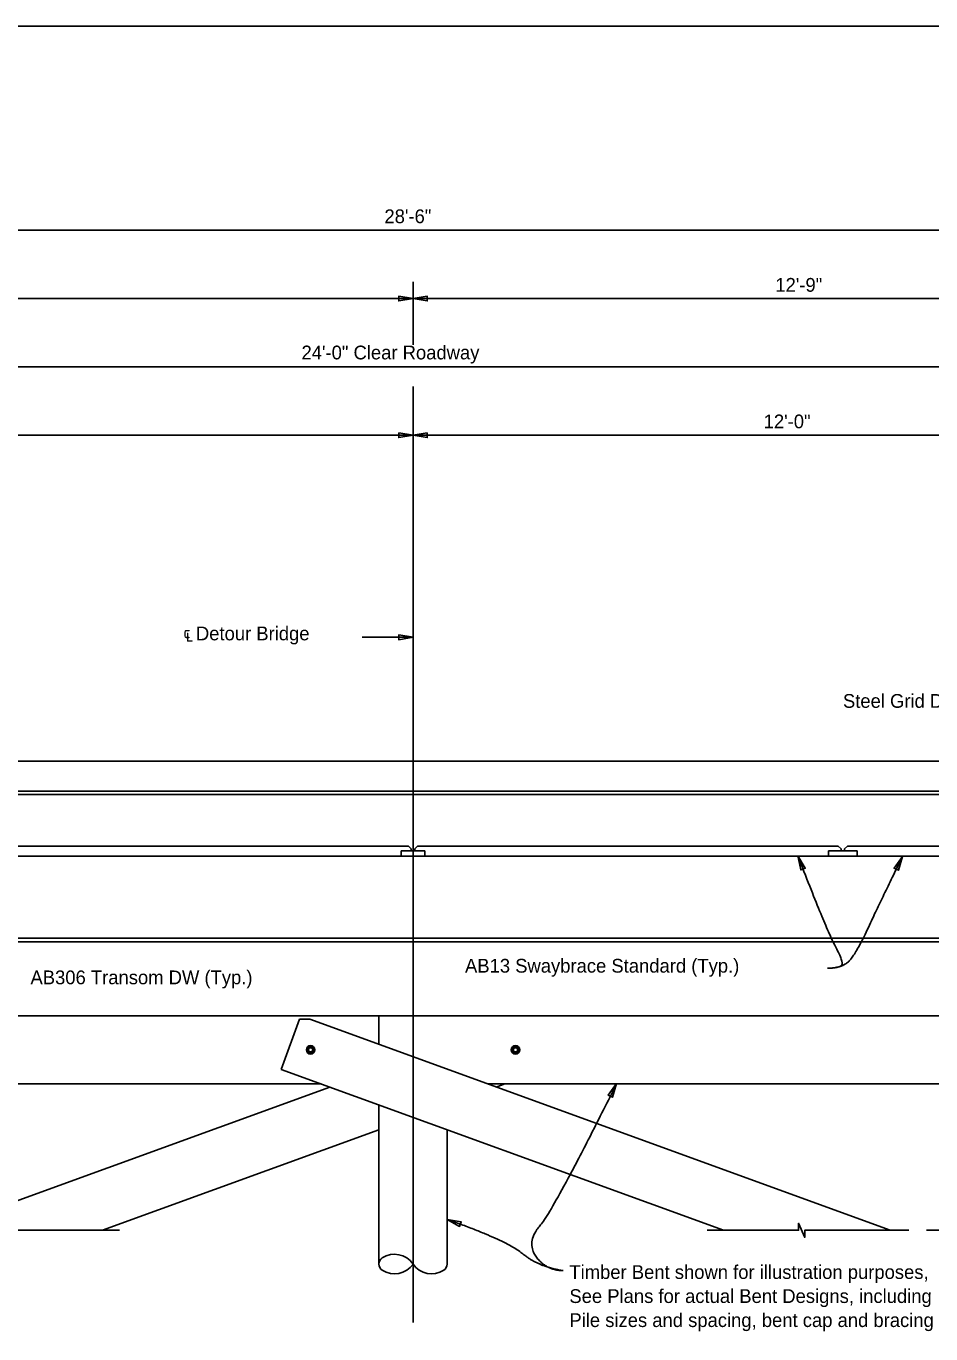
# Model space of a CAD drawing. Extents: x 11137.4 to 11208.2, y 76297.7 to 76332.4.
# Drawn here: x 11151.28 to 11164.53, y 76313.02 to 76332.16 of the extents above; entities that cross this region are included whole.
import ezdxf

# ---------------------------------------------------------------- set-up
doc = ezdxf.new("R2010")
doc.units = 0
for name, color, linetype in [('ActivePts-ConstElements', 7, 'Continuous'), ('CL_Minor', 7, 'Continuous'), ('Dimension', 7, 'Continuous'), ('Miscellaneous', 7, 'Continuous'), ('SteelMisc', 7, 'Continuous'), ('Symbols', 7, 'Continuous'), ('TextStructures', 7, 'Continuous'), ('Wood', 7, 'Continuous')]:
    doc.layers.add(name, color=color, linetype=linetype)

msp = doc.modelspace()

# ---------------------------------------------------------------- linework, layer by layer
at = {"layer": 'ActivePts-ConstElements'}
msp.add_lwpolyline([(11137.439, 76306.213), (11178.49, 76306.213), (11178.49, 76332.159), (11137.439, 76332.159)], close=True, dxfattribs=at)
at = {"layer": 'CL_Minor'}
for points in [[(11156.946, 76327.493), (11156.946, 76328.414)], [(11156.946, 76313.182), (11156.946, 76326.884)]]:
    msp.add_lwpolyline(points, dxfattribs=at)
at = {"layer": 'Dimension'}
for p, q in [((11142.696, 76329.171), (11171.196, 76329.171)), ((11142.696, 76328.171), (11171.196, 76328.171)), ((11144.946, 76327.171), (11168.946, 76327.171)), ((11144.946, 76326.171), (11168.946, 76326.171)), ((11156.199, 76323.213), (11156.946, 76323.213))]:
    msp.add_line(p, q, dxfattribs=at)
for points in [[(11156.946, 76328.171), (11156.737, 76328.136), (11156.737, 76328.206)], [(11156.946, 76328.171), (11157.154, 76328.136), (11157.154, 76328.206)], [(11156.737, 76326.206), (11156.946, 76326.171), (11156.737, 76326.136)], [(11157.154, 76326.206), (11156.946, 76326.171), (11157.154, 76326.136)], [(11156.946, 76323.213), (11156.737, 76323.248), (11156.737, 76323.177)], [(11162.58, 76320.013), (11162.622, 76319.806), (11162.688, 76319.831)], [(11164.113, 76320.003), (11163.989, 76319.832), (11164.052, 76319.801)], [(11159.927, 76316.68), (11159.803, 76316.509), (11159.866, 76316.478)], [(11157.444, 76314.691), (11157.628, 76314.588), (11157.652, 76314.655)]]:
    msp.add_lwpolyline(points, close=True, dxfattribs=at)
for points in [[(11163.014, 76318.368), (11163.149, 76318.368), (11163.269, 76318.431), (11163.004, 76318.913), (11162.58, 76320.013)], [(11163.014, 76318.368), (11163.226, 76318.368), (11163.429, 76318.571), (11163.819, 76319.41), (11164.113, 76320.003)], [(11159.146, 76313.941), (11158.895, 76313.941), (11158.596, 76314.356), (11159.011, 76314.838), (11159.927, 76316.68)], [(11159.146, 76313.941), (11158.779, 76313.996), (11158.321, 76314.382), (11157.444, 76314.691)]]:
    msp.add_open_spline(points, degree=2, dxfattribs=at)
at = {"layer": 'Miscellaneous'}
msp.add_line((11168.946, 76321.4), (11144.946, 76321.4), dxfattribs=at)
at = {"layer": 'SteelMisc'}
for p, q in [((11144.344, 76320.962), (11169.547, 76320.962)), ((11144.344, 76320.91), (11169.547, 76320.91)), ((11150.721, 76320.156), (11156.878, 76320.156)), ((11156.773, 76320.087), (11157.119, 76320.087)), ((11156.773, 76320.087), (11156.773, 76320.006)), ((11156.773, 76320.087), (11156.773, 76320.006)), ((11157.119, 76320.087), (11156.773, 76320.087)), ((11156.878, 76320.156), (11156.92, 76320.114)), ((11156.92, 76320.114), (11156.92, 76320.087)), ((11157.013, 76320.156), (11156.971, 76320.114)), ((11156.971, 76320.114), (11156.971, 76320.087)), ((11163.17, 76320.156), (11157.013, 76320.156)), ((11157.119, 76320.087), (11157.119, 76320.006)), ((11157.119, 76320.087), (11157.119, 76320.006)), ((11163.447, 76320.087), (11163.028, 76320.087)), ((11163.028, 76320.087), (11163.028, 76320.006)), ((11163.17, 76320.156), (11163.212, 76320.114)), ((11163.212, 76320.114), (11163.212, 76320.087)), ((11163.305, 76320.156), (11163.263, 76320.114)), ((11163.263, 76320.114), (11163.263, 76320.087)), ((11163.305, 76320.156), (11169.17, 76320.156)), ((11163.447, 76320.087), (11163.447, 76320.006)), ((11150.664, 76320.006), (11157.119, 76320.006)), ((11163.228, 76320.006), (11156.773, 76320.006)), ((11162.955, 76320.006), (11169.374, 76320.006)), ((11146.356, 76318.806), (11167.535, 76318.806)), ((11146.356, 76318.754), (11167.535, 76318.754)), ((11141.782, 76317.673), (11172.135, 76317.673))]:
    msp.add_line(p, q, dxfattribs=at)
for points in [[(11155.493, 76317.2), (11155.493, 76317.146), (11155.446, 76317.118), (11155.398, 76317.146), (11155.398, 76317.2), (11155.446, 76317.228)], [(11158.493, 76317.2), (11158.493, 76317.146), (11158.446, 76317.118), (11158.398, 76317.146), (11158.398, 76317.2), (11158.446, 76317.228)]]:
    msp.add_lwpolyline(points, close=True, dxfattribs=at)
for centre, radius in [((11155.446, 76317.173), 0.0612), ((11155.446, 76317.173), 0.0474), ((11155.446, 76317.173), 0.0312), ((11158.446, 76317.173), 0.0612), ((11158.446, 76317.173), 0.0474), ((11158.446, 76317.173), 0.0312)]:
    msp.add_circle(centre, radius, dxfattribs=at)
at = {"layer": 'Symbols'}
for points in [[(11149.848, 76314.531), (11150.937, 76314.531), (11150.937, 76314.634), (11151.027, 76314.427), (11151.027, 76314.531), (11152.648, 76314.531)], [(11161.254, 76314.531), (11162.591, 76314.531), (11162.591, 76314.634), (11162.681, 76314.427), (11162.681, 76314.531), (11164.207, 76314.531)], [(11164.465, 76314.531), (11165.982, 76314.531), (11165.982, 76314.634), (11166.072, 76314.427), (11166.072, 76314.531), (11167.33, 76314.531)]]:
    msp.add_lwpolyline(points, dxfattribs=at)
at = {"layer": 'Wood'}
for p, q in [((11139.446, 76317.673), (11156.946, 76317.673)), ((11155.017, 76316.886), (11155.284, 76317.621)), ((11155.433, 76317.621), (11155.284, 76317.621)), ((11163.931, 76314.531), (11155.433, 76317.621)), ((11156.446, 76317.253), (11156.446, 76317.673)), ((11174.446, 76317.673), (11156.946, 76317.673)), ((11161.493, 76314.531), (11155.017, 76316.886)), ((11143.466, 76316.673), (11155.601, 76316.673)), ((11174.446, 76316.673), (11158.04, 76316.673)), ((11158.165, 76316.628), (11158.29, 76316.673)), ((11149.96, 76314.531), (11155.726, 76316.628)), ((11156.446, 76314.036), (11156.446, 76316.366)), ((11152.398, 76314.531), (11156.446, 76316.002)), ((11157.446, 76314.036), (11157.446, 76316.002))]:
    msp.add_line(p, q, dxfattribs=at)
for centre, radius, start, end in [((11156.674, 76313.851), 0.329, 34.3251, 123.0426), ((11156.553, 76314.036), 0.107, 122.6152, 179.9979), ((11156.553, 76314.036), 0.107, 179.9979, 237.3848), ((11156.674, 76314.222), 0.329, 236.955, 325.6725), ((11157.217, 76314.222), 0.329, 214.3153, 303.0328), ((11157.339, 76314.036), 0.107, 302.6152, 0.0021)]:
    msp.add_arc(centre, radius, start, end, dxfattribs=at)

# ---------------------------------------------------------------- texts
at = {"layer": 'Dimension'}
msp.add_text('12\'-0"', height=0.2016, dxfattribs=at).set_placement((11162.079, 76326.272))
at = {"layer": 'TextStructures'}
for s, p in [('28\'-6"', (11156.527, 76329.275)), ('12\'-9"', (11162.25, 76328.271)), ('24\'-0" Clear Roadway', (11155.313, 76327.281)), ('℄ Detour Bridge', (11153.583, 76323.168)), ('Steel Grid Deck & Curb', (11163.24, 76322.18)), ('AB13 Swaybrace Standard (Typ.)', (11157.707, 76318.303)), ('AB306 Transom DW (Typ.)', (11151.345, 76318.133)), ('Timber Bent shown for illustration purposes, ', (11159.235, 76313.819)), ('See Plans for actual Bent Designs, including ', (11159.235, 76313.467)), ('Pile sizes and spacing, bent cap and bracing ', (11159.235, 76313.115))]:
    msp.add_text(s, height=0.2016, dxfattribs=at).set_placement(p)

doc.saveas('drawing.dxf')
